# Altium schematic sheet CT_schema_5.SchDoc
size 411 x 401 mm
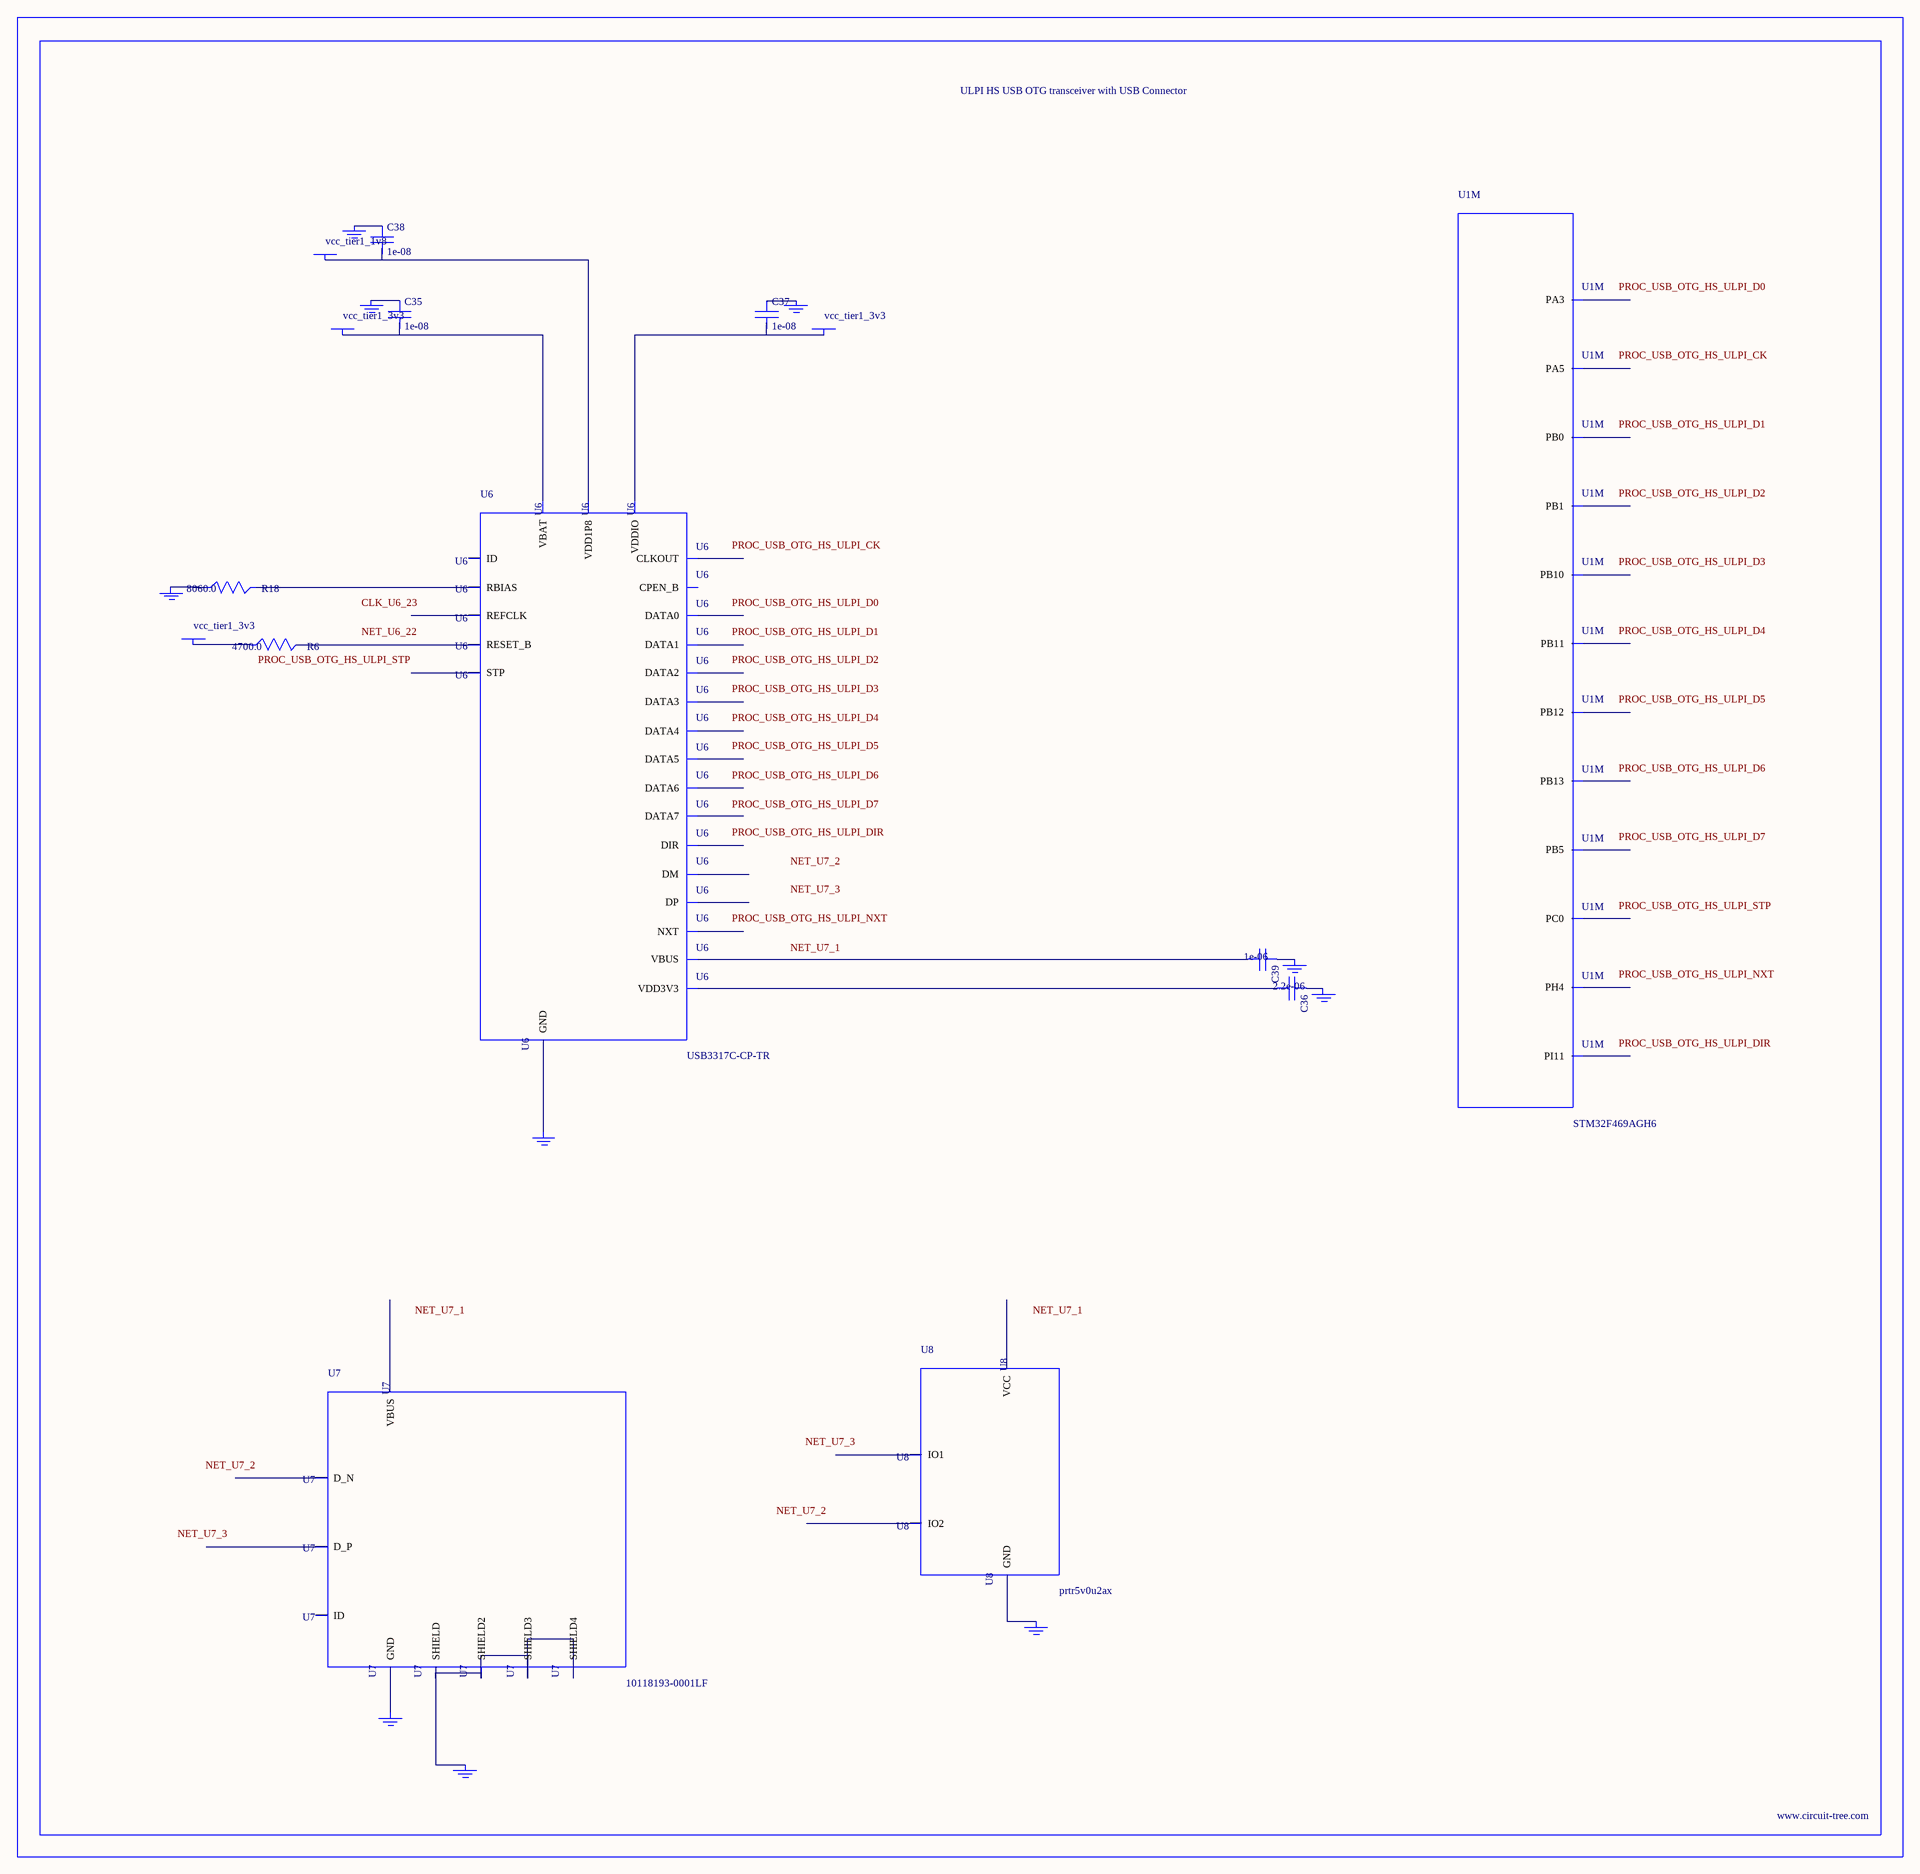
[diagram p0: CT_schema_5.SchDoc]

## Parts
BORDER4  (no value)
C35  1e-08  [C0402]
C36  2.2e-06  [C0603]
C37  1e-08  [C0402]
C38  1e-08  [C0402]
C39  1e-06  [C0603]
GND_INSTANCE_4_0  (no value)
GND_INSTANCE_4_1  (no value)
GND_INSTANCE_4_2  (no value)
GND_INSTANCE_4_3  (no value)
GND_INSTANCE_4_4  (no value)
GND_INSTANCE_4_5  (no value)
GND_INSTANCE_4_6  (no value)
GND_INSTANCE_4_7  (no value)
GND_INSTANCE_4_8  (no value)
GND_INSTANCE_4_9  (no value)
POWER_INSTANCE_4_0  vcc_tier1_3v3
POWER_INSTANCE_4_1  vcc_tier1_3v3
POWER_INSTANCE_4_2  vcc_tier1_1v8
POWER_INSTANCE_4_3  vcc_tier1_3v3
R6  4700.0  [R0603]
R18  8060.0  [R0603]
U1  STM32F469AGH6  [UFBGA169]  (part M of 14)
U6  USB3317C-CP-TR  [QFN-24]
U7  10118193-0001LF  [FCI_10118193-0001LF]
U8  prtr5v0u2ax  [SOT143B]

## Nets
NetC35_1: C35.1 GND_INSTANCE_4_1.0(GND)
NetC35_2: C35.2 POWER_INSTANCE_4_0.0(PWR) U6.3(VBAT)
NetC36_1: C36.1 GND_INSTANCE_4_2.0(GND)
NetC36_2: C36.2 U6.4(VDD3V3)
NetC37_1: C37.1 GND_INSTANCE_4_3.0(GND)
NetC37_2: C37.2 POWER_INSTANCE_4_1.0(PWR) U6.17(VDDIO)
NetC38_1: C38.1 GND_INSTANCE_4_4.0(GND)
NetC38_2: C38.2 POWER_INSTANCE_4_2.0(PWR) U6.21(VDD1P8)
NetC39_1: C39.1 GND_INSTANCE_4_0.0(GND)
NetC39_2: C39.2 U6.2(VBUS)
NetGND_INSTANCE_4_5_0: GND_INSTANCE_4_5.0(GND) R18.1
NetGND_INSTANCE_4_6_0: GND_INSTANCE_4_6.0(GND) U6.25(GND)
NetGND_INSTANCE_4_7_0: GND_INSTANCE_4_7.0(GND) U7.6(SHIELD) U7.7(SHIELD2) U7.8(SHIELD3) U7.9(SHIELD4)
NetGND_INSTANCE_4_8_0: GND_INSTANCE_4_8.0(GND) U7.5(GND)
NetGND_INSTANCE_4_9_0: GND_INSTANCE_4_9.0(GND) U8.1(GND)
NetPOWER_INSTANCE_4_3_0: POWER_INSTANCE_4_3.0(PWR) R6.1
NetR6_2: R6.2 U6.22(RESET_B)
NetR18_2: R18.2 U6.24(RBIAS)

Not connected (* = marked no-connect by the designer): U1 D5(PB5) F2(PI11) K3(PA3) K5(PB1) M1(PC0) M2(PH4) M3(PA5) M8(PB10) N4(PB0) N8(PB11) N10(PB12) N11(PB13); U6 1(ID) 5(DM) 6(DP) 7(CPEN_B) 8(DATA7) 9(DATA6) 10(DATA5) 11(DATA4) 12(CLKOUT) 13(DATA3) 14(DATA2) 15(DATA1) 16(DATA0) 18(NXT) 19(DIR) 20(STP) 23(REFCLK); U7 1(VBUS) 2(D_N) 3(D_P) 4(ID); U8 2(IO1) 3(IO2) 4(VCC)

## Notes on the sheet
- Labels drawn without touching a wire or pin: CLK_U6_23, NET_U6_22, NET_U7_1, NET_U7_2, NET_U7_3, PROC_USB_OTG_HS_ULPI_CK, PROC_USB_OTG_HS_ULPI_D0, PROC_USB_OTG_HS_ULPI_D1, PROC_USB_OTG_HS_ULPI_D2, PROC_USB_OTG_HS_ULPI_D3, PROC_USB_OTG_HS_ULPI_D4, PROC_USB_OTG_HS_ULPI_D5, PROC_USB_OTG_HS_ULPI_D6, PROC_USB_OTG_HS_ULPI_D7, PROC_USB_OTG_HS_ULPI_DIR, PROC_USB_OTG_HS_ULPI_NXT, PROC_USB_OTG_HS_ULPI_STP

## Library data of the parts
BORDER4 = BORDER_PAGE4
C35 C37 C38 = C0402C103K3RAC
C36 = C0603C225K8RACTU
C39 = C0603C105K3RACTU
GND_INSTANCE_4_0-GND_INSTANCE_4_9 = GND
POWER_INSTANCE_4_0-POWER_INSTANCE_4_3 = PWR
R6 = RC0603JR-074K7L
R18 = ERJ-3EKF8061V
